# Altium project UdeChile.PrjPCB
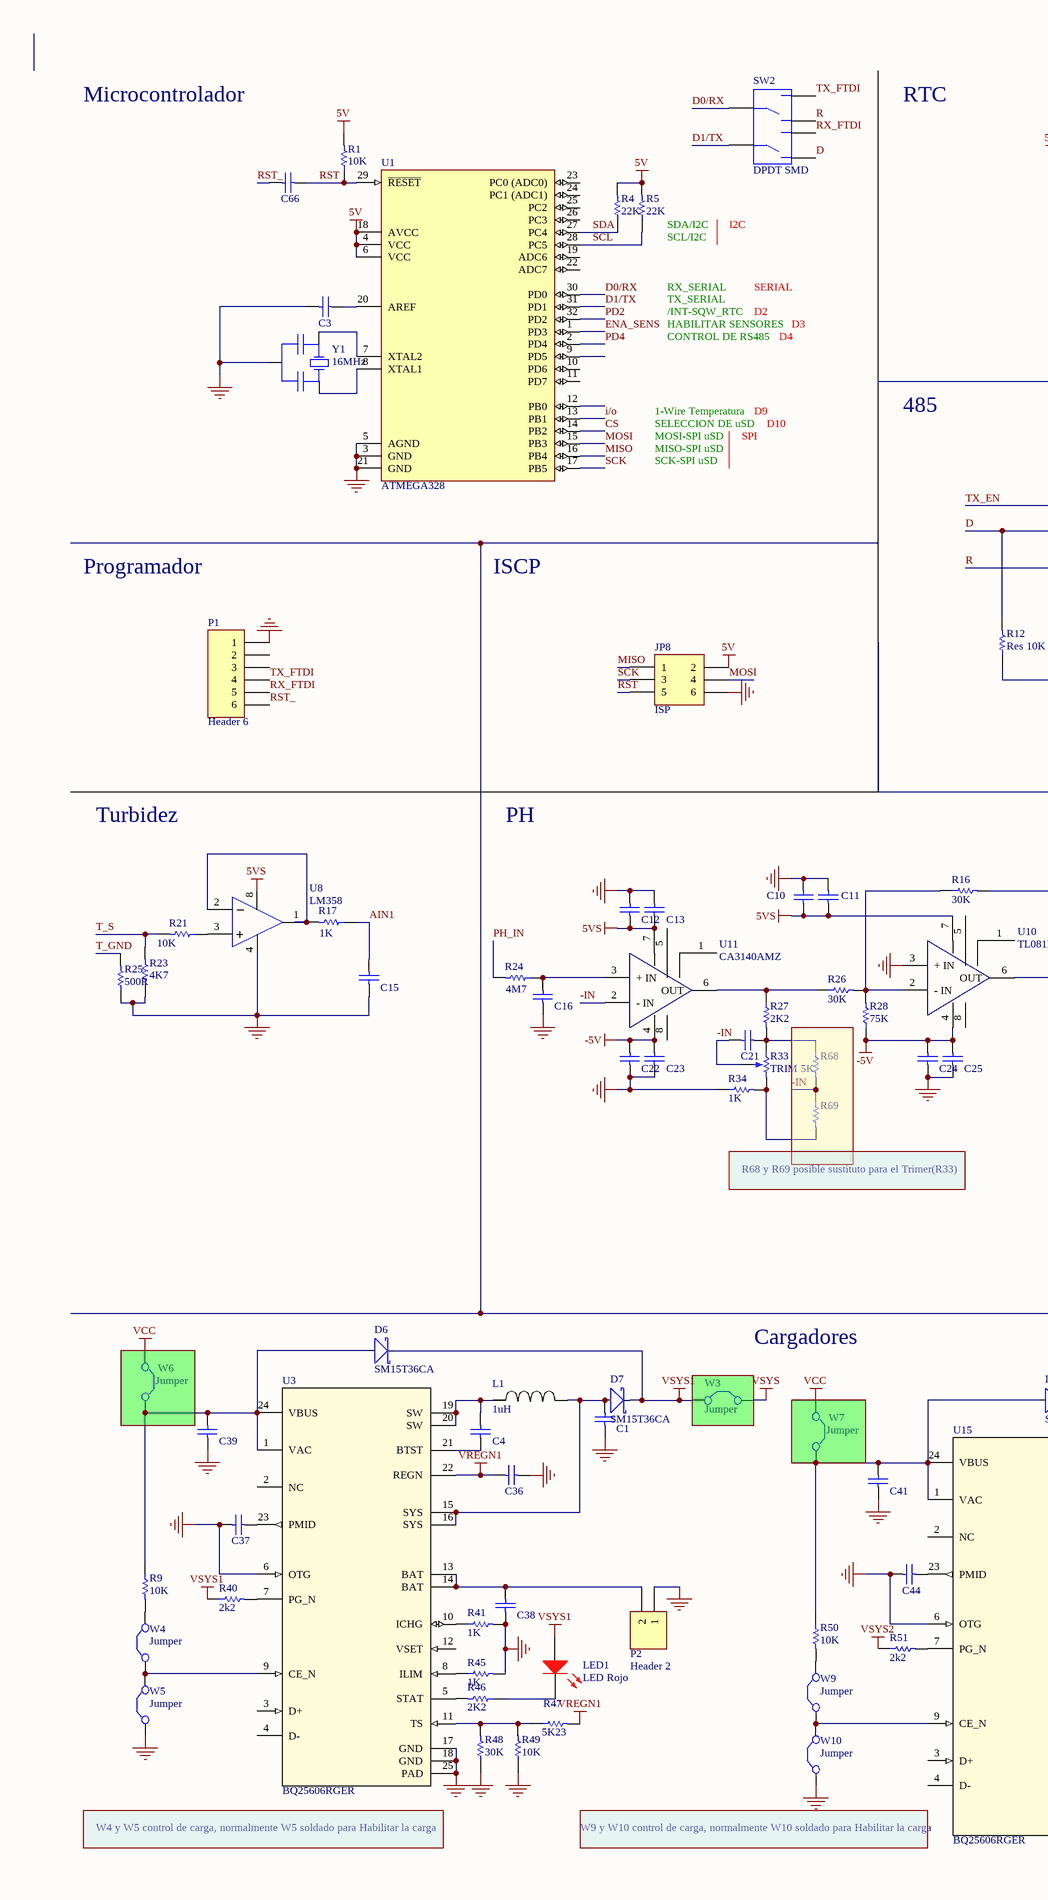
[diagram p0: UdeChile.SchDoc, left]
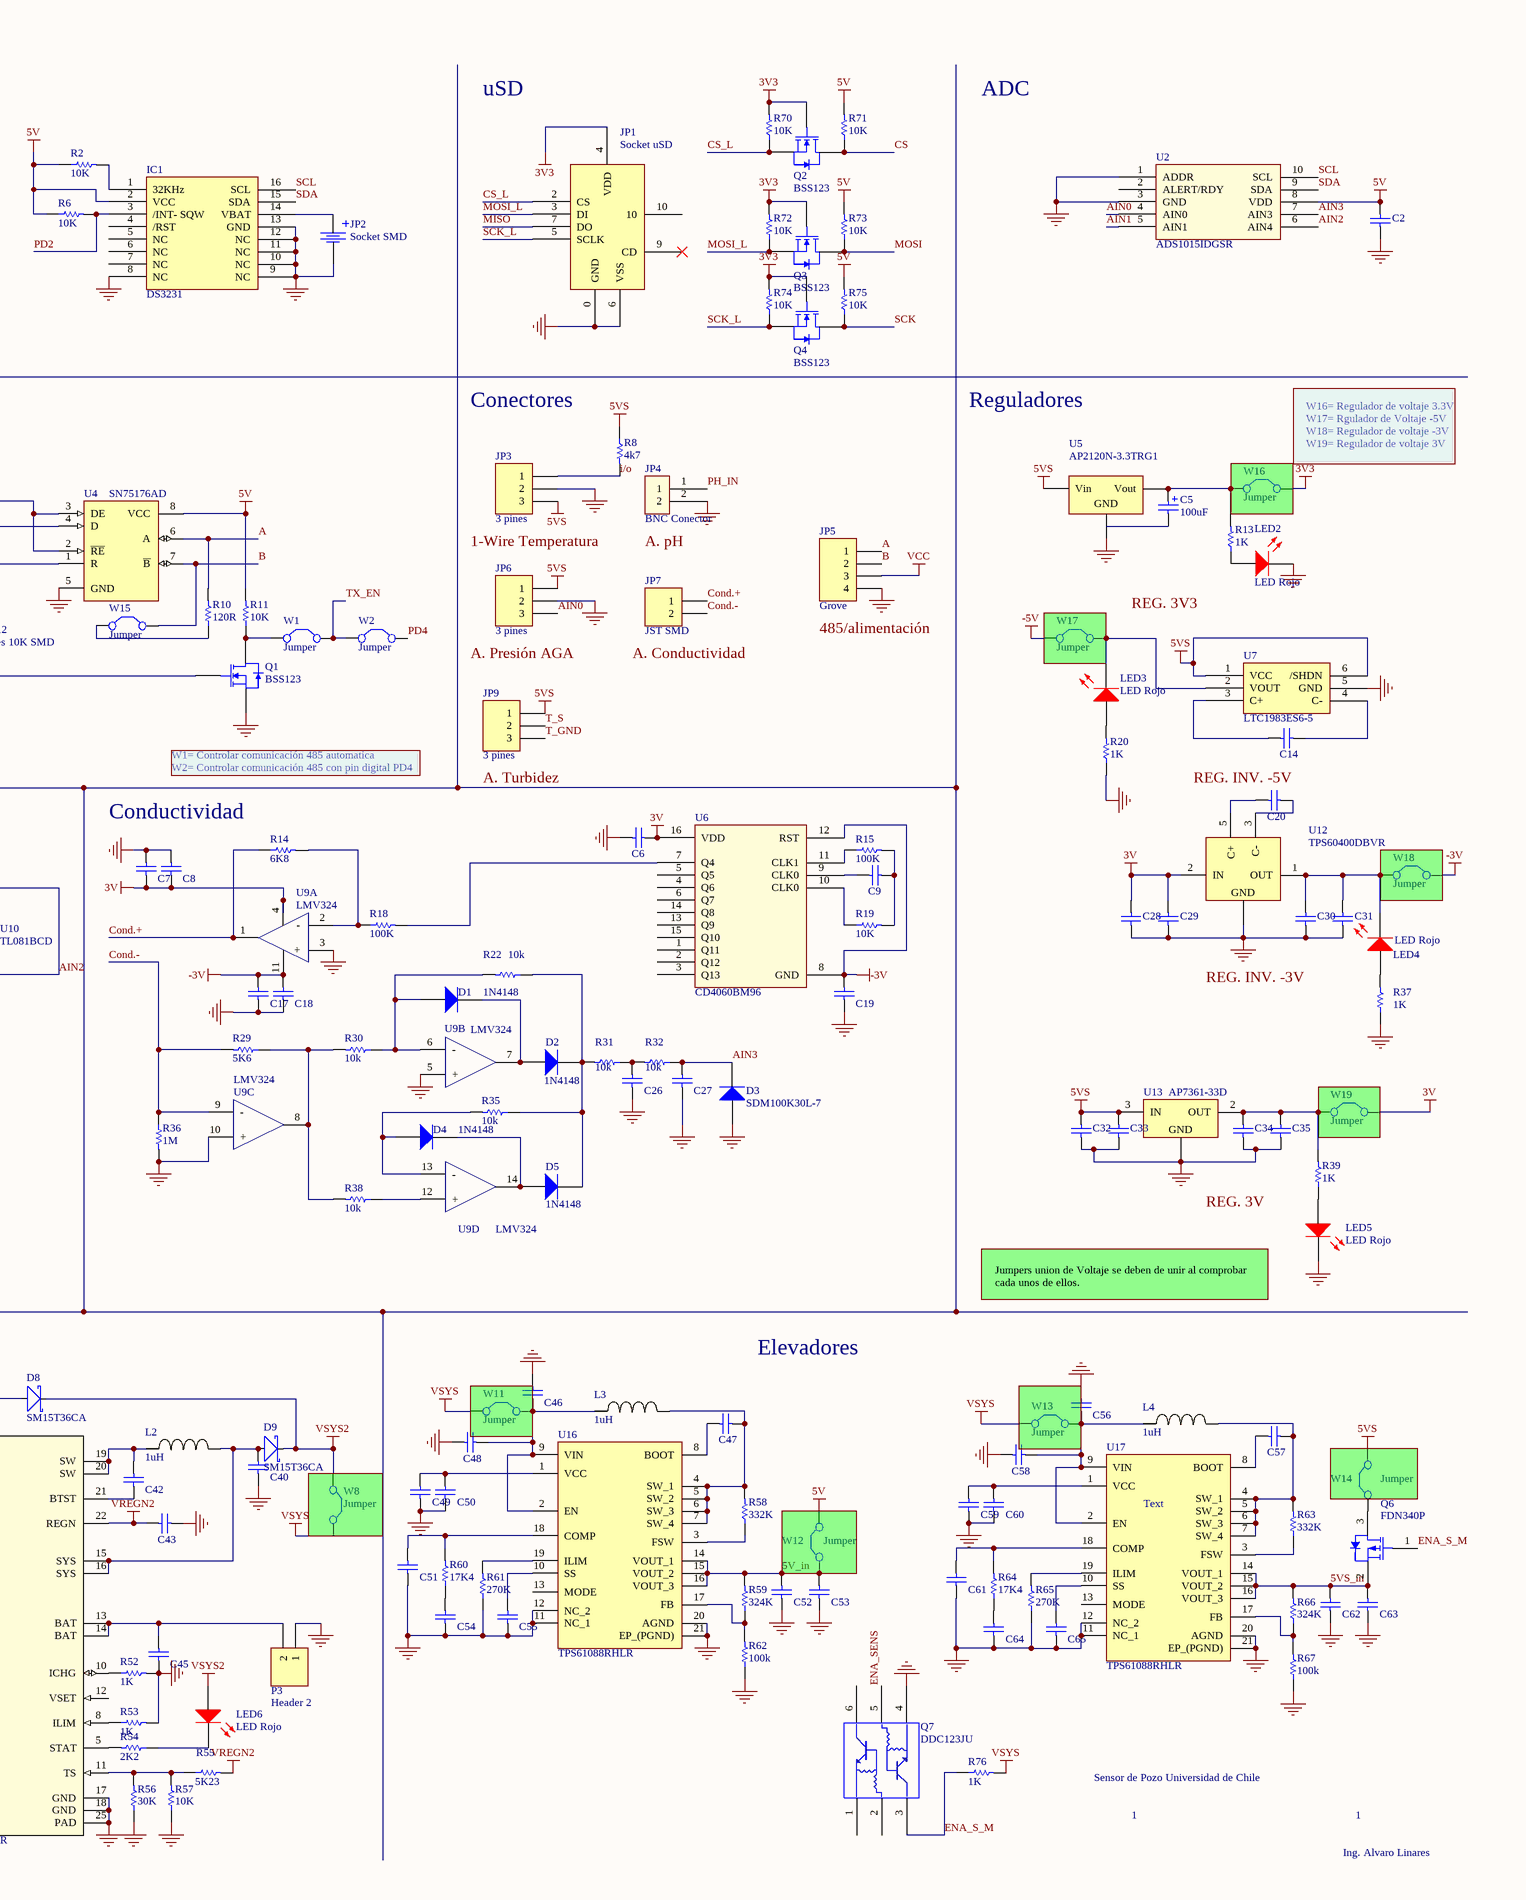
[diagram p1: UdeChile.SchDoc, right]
1 sheet, 212 parts. Net scope: global (net labels, ports and power ports of the same name join across sheets).
Board file: UdeChile.PcbDoc

## Sheet UdeChile.SchDoc
size C

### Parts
C1  0.1uF  [Cap 0.1uF 0603 SMD]  (value not drawn)
C2  0.1uF  [Cap 0.1uF 0603 SMD]  (value not drawn)
C3  0.1uF  [Cap 0.1uF 0603 SMD]  (value not drawn)
C4  47nF  [Cap 0.1uF 0603 SMD]  (value not drawn)
C5  100uF  [Cap tant 10uF 1206 SMD]
C6  0.1uF  [Cap 0.1uF 0603 SMD]  (value not drawn)
C7  4.7uF  [Cap 0.1uF 0603 SMD]  (value not drawn)
C8  0.1uF  [Cap 0.1uF 0603 SMD]  (value not drawn)
C9  1nF  [Cap 0.1uF 0603 SMD]  (value not drawn)
C10  0.1uF  [Cap 0.1uF 0603 SMD]  (value not drawn)
C11  10uF  [Cap 0.1uF 0603 SMD]  (value not drawn)
C12  0.1uF  [Cap 0.1uF 0603 SMD]  (value not drawn)
C13  10uF  [Cap 0.1uF 0603 SMD]  (value not drawn)
C14  0.1uF  [Cap 0.1uF 0603 SMD]  (value not drawn)
C15  0.1uF  [Cap 0.1uF 0603 SMD]  (value not drawn)
C16  2.2nF  [Cap 0.1uF 0603 SMD]  (value not drawn)
C17  4.7uF  [Cap 0.1uF 0603 SMD]  (value not drawn)
C18  0.1uF  [Cap 0.1uF 0603 SMD]  (value not drawn)
C19  0.1uF  [Cap 0.1uF 0603 SMD]  (value not drawn)
C20  0.1uF  [Cap 0.1uF 0603 SMD]  (value not drawn)
C21  1uF  [Cap 0.1uF 0603 SMD]  (value not drawn)
C22  0.1uF  [Cap 0.1uF 0603 SMD]  (value not drawn)
C23  10uF  [Cap 0.1uF 0603 SMD]  (value not drawn)
C24  0.1uF  [Cap 0.1uF 0603 SMD]  (value not drawn)
C25  10uF  [Cap 0.1uF 0603 SMD]  (value not drawn)
C26  1uF  [Cap 0.1uF 0603 SMD]  (value not drawn)
C27  1uF  [Cap 0.1uF 0603 SMD]  (value not drawn)
C28  0.1uF  [Cap 0.1uF 0603 SMD]  (value not drawn)
C29  0.1uF  [Cap 0.1uF 0603 SMD]  (value not drawn)
C30  0.1uF  [Cap 0.1uF 0603 SMD]  (value not drawn)
C31  0.1uF  [Cap 0.1uF 0603 SMD]  (value not drawn)
C32  0.1uF  [Cap 0.1uF 0603 SMD]  (value not drawn)
C33  0.1uF  [Cap 0.1uF 0603 SMD]  (value not drawn)
C34  0.1uF  [Cap 0.1uF 0603 SMD]  (value not drawn)
C35  0.1uF  [Cap 0.1uF 0603 SMD]  (value not drawn)
C36  4.7uF  [Cap 0.1uF 0603 SMD]  (value not drawn)
C37  10uF  [Cap 0.1uF 0603 SMD]  (value not drawn)
C38  10uF  [Cap 0.1uF 0603 SMD]  (value not drawn)
C39  10uF  [Cap 0.1uF 0603 SMD]  (value not drawn)
C40  0.1uF  [Cap 0.1uF 0603 SMD]  (value not drawn)
C41  10uF  [Cap 0.1uF 0603 SMD]  (value not drawn)
C42  47nF  [Cap 0.1uF 0603 SMD]  (value not drawn)
C43  4.7uF  [Cap 0.1uF 0603 SMD]  (value not drawn)
C44  10uF  [Cap 0.1uF 0603 SMD]  (value not drawn)
C45  10uF  [Cap 0.1uF 0603 SMD]  (value not drawn)
C46  0.1uF  [Cap 0.1uF 0603 SMD]  (value not drawn)
C47  0.1uF  [Cap 0.1uF 0603 SMD]  (value not drawn)
C48  47uF  [Cap 0.1uF 0603 SMD]  (value not drawn)
C49  1uF  [Cap 0.1uF 0603 SMD]  (value not drawn)
C50  1uF  [Cap 0.1uF 0603 SMD]  (value not drawn)
C51  51pF  [Cap 0.1uF 0603 SMD]  (value not drawn)
C52  47uF  [Cap 0.1uF 0603 SMD]  (value not drawn)
C53  47uF  [Cap 0.1uF 0603 SMD]  (value not drawn)
C54  1nF  [Cap 0.1uF 0603 SMD]  (value not drawn)
C55  82nF  [Cap 0.1uF 0603 SMD]  (value not drawn)
C56  0.1uF  [Cap 0.1uF 0603 SMD]  (value not drawn)
C57  0.1uF  [Cap 0.1uF 0603 SMD]  (value not drawn)
C58  47uF  [Cap 0.1uF 0603 SMD]  (value not drawn)
C59  1uF  [Cap 0.1uF 0603 SMD]  (value not drawn)
C60  1uF  [Cap 0.1uF 0603 SMD]  (value not drawn)
C61  51pF  [Cap 0.1uF 0603 SMD]  (value not drawn)
C62  47uF  [Cap 0.1uF 0603 SMD]  (value not drawn)
C63  47uF  [Cap 0.1uF 0603 SMD]  (value not drawn)
C64  1nF  [Cap 0.1uF 0603 SMD]  (value not drawn)
C65  82nF  [Cap 0.1uF 0603 SMD]  (value not drawn)
C66  0.1uF  [Cap 0.1uF 0603 SMD]  (value not drawn)
D1  1N4148  [Diodo 1N4148 SMD]
D2  1N4148  [Diodo 1N4148 SMD]
D3  SDM100K30L-7  [Diodo SDM100K30L-7 SMD]
D4  1N4148  [Diodo 1N4148 SMD]
D5  1N4148  [Diodo 1N4148 SMD]
D6  SM15T36CA  [SM15T36CA]
D7  SM15T36CA  [SM15T36CA]
D8  SM15T36CA  [SM15T36CA]
D9  SM15T36CA  [SM15T36CA]
IC1  DS3231  [RTC DS323116-SOIC]
JP1  Socket uSD  [uSD Socket]
JP2  Socket SMD  [Socket Pila 12mm SMD]
JP3  3 pines  [JST SMD 3 PINES]
JP4  BNC Conector  [BNC Conector]
JP5  Grove  [JST TH 4 Pines - Horizontal]
JP6  3 pines  [JST SMD 3 PINES]
JP7  JST SMD  [JST SMD 2 pines - 2.54mm]
JP8  ISP  [HDR2X3]
JP9  3 pines  [JST SMD 3 PINES - 2.54mm]
L1  1uH  [74438336010]
L2  1uH  [74438336010]
L3  1uH  [SRN8040-1R0Y]
L4  1uH  [SRN8040-1R0Y]
LED1  LED Rojo  [LED Rojo 0603]
LED2  LED Rojo  [LED Rojo 0603]
LED3  LED Rojo  [LED Rojo 0603]
LED4  LED Rojo  [LED Rojo 0603]
LED5  LED Rojo  [LED Rojo 0603]
LED6  LED Rojo  [LED Rojo 0603]
P1  Header 6  [HDR1X6]
P2  Header 2  [HDR1X2]
P3  Header 2  [HDR1X2]
Q1  BSS123  [MOSFET BSS123  SMD SOT-23]
Q2  BSS123  [MOSFET BSS123  SMD SOT-23]
Q3  BSS123  [MOSFET BSS123  SMD SOT-23]
Q4  BSS123  [MOSFET BSS123  SMD SOT-23]
Q6  FDN340P  [MOSFET FDN340P SSOT3]
Q7  DDC123JU  [Transistor array DDC123JU-FDICT SMD]
R1  10K  [Res 1K 0603 1/8W]
R2  10K  [Res 10K 0603 1/10W]
R4  22K  [Res 1K 0603 1/8W]
R5  22K  [Res 1K 0603 1/8W]
R6  10K  [Res 10K 0603 1/10W]
R8  4k7  [Res 10K 0603 1/10W]
R9  10K  [Res 1K 0603 1/8W]
R10  120R  [Res 1K 0603 1/8W]
R11  10K  [Res 10K 0603 1/10W]
R12  Res 10K SMD  [Res 10K 0603 1/10W]
R13  1K  [Res 1K 0603 1/8W]
R14  6K8  [Res 1K 0603 1/8W]
R15  100K  [Res 1K 0603 1/8W]
R16  30K  [Res 1K 0603 1/8W]
R17  1K  [Res 1K 0603 1/8W]
R18  100K  [Res 1K 0603 1/8W]
R19  10K  [Res 1K 0603 1/8W]
R20  1K  [Res 1K 0603 1/8W]
R21  10K  [Res 1K 0603 1/8W]
R22  10k  [Res 1K 0603 1/8W]
R23  4K7  [Res 1K 0603 1/8W]
R24  4M7  [Res 1K 0603 1/8W]
R25  500R  [Res 1K 0603 1/8W]
R26  30K  [Res 1K 0603 1/8W]
R27  2K2  [Res 1K 0603 1/8W]
R28  75K  [Res 1K 0603 1/8W]
R29  5K6  [Res 1K 0603 1/8W]
R30  10k  [Res 1K 0603 1/8W]
R31  10k  [Res 1K 0603 1/8W]
R32  10k  [Res 1K 0603 1/8W]
R33  TRIM 5K  [TRIMPOT TH]
R34  1K  [Res 1K 0603 1/8W]
R35  10k  [Res 1K 0603 1/8W]
R36  1M  [Res 1K 0603 1/8W]
R37  1K  [Res 1K 0603 1/8W]
R38  10k  [Res 1K 0603 1/8W]
R39  1K  [Res 1K 0603 1/8W]
R40  2k2  [Res 1K 0603 1/8W]
R41  1K  [Res 1K 0603 1/8W]
R45  1K  [Res 1K 0603 1/8W]
R46  2K2  [Res 1K 0603 1/8W]
R47  5K23  [Res 1K 0603 1/8W]
R48  30K  [Res 1K 0603 1/8W]
R49  10K  [Res 1K 0603 1/8W]
R50  10K  [Res 1K 0603 1/8W]
R51  2k2  [Res 1K 0603 1/8W]
R52  1K  [Res 1K 0603 1/8W]
R53  1K  [Res 1K 0603 1/8W]
R54  2K2  [Res 1K 0603 1/8W]
R55  5K23  [Res 1K 0603 1/8W]
R56  30K  [Res 1K 0603 1/8W]
R57  10K  [Res 1K 0603 1/8W]
R58  332K  [Res 1K 0603 1/8W]
R59  324K  [Res 1K 0603 1/8W]
R60  17K4  [Res 1K 0603 1/8W]
R61  270K  [Res 1K 0603 1/8W]
R62  100k  [Res 1K 0603 1/8W]
R63  332K  [Res 1K 0603 1/8W]
R64  17K4  [Res 1K 0603 1/8W]
R65  270K  [Res 1K 0603 1/8W]
R66  324K  [Res 1K 0603 1/8W]
R67  100k  [Res 1K 0603 1/8W]
R68  0  [Res 1K 0603 1/8W]  (value not drawn)
R69  0  [Res 1K 0603 1/8W]  (value not drawn)
R70  10K  [Res 10K 0603 1/10W]
R71  10K  [Res 10K 0603 1/10W]
R72  10K  [Res 10K 0603 1/10W]
R73  10K  [Res 10K 0603 1/10W]
R74  10K  [Res 10K 0603 1/10W]
R75  10K  [Res 10K 0603 1/10W]
R76  1K  [Res 1K 0603 1/8W]
SW2  DPDT SMD  [SW INTERR SMD]
U1  ATMEGA328  [ATMega328 32-TQFP SMD]
U2  ADS1015IDGSR  [ADS1015IDGSR]
U3  BQ25606RGER  [BQ25606RGER]
U4  SN75176AD  [Transceiver SN75176AD SOCI8]
U5  AP2120N-3.3TRG1  [Reg 3.3V 150mA SOT-23]
U6  CD4060BM96  [C BINARY COUNTER/DIV/OSC CD4060BM 16SOIC]
U7  LTC1983ES6-5  [Reg CHARGE PUMP -5V SOT-23-6]
U8  LM358  [Op Amp LM358 8-SOIC SMD]
U9  LMV324  [Op. Amp LM324 SO-14]  (parts A,B,C,D of 4)
U10  TL081BCD  [Amp. Op. CA3140AMZ SOIC8]
U11  CA3140AMZ  [Amp. Op. CA3140AMZ SOIC8]
U12  TPS60400DBVR  [Charge Pump Switching Regulator - TPS60400DBVR]
U13  AP7361-33D  [Reg 3V 300mA SOT23-3]
U15  BQ25606RGER  [BQ25606RGER]
U16  TPS61088RHLR  [TPS61088RHLR]
U17  TPS61088RHLR  [TPS61088RHLR]
W1  Jumper  [Jumper]
W2  Jumper  [Jumper]
W3  Jumper  [Jumper]
W4  Jumper  [Jumper]
W5  Jumper  [Jumper]
W6  Jumper  [Jumper]
W7  Jumper  [Jumper]
W8  Jumper  [Jumper]
W9  Jumper  [Jumper]
W10  Jumper  [Jumper]
W11  Jumper  [Jumper]
W12  Jumper  [Jumper]
W13  Jumper  [Jumper]
W14  Jumper  [Jumper]
W15  Jumper  [Jumper]
W16  Jumper  [Jumper]
W17  Jumper  [Jumper]
W18  Jumper  [Jumper]
W19  Jumper  [Jumper]
Y1  16MHz  [Xtal 16MHz SMD]

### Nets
3V: C6.1 C7.2 C8.2 C28.2 C29.2 U6.16(VDD) U9.4(V+) U12.2(IN) W19.2
3V3: JP1.4(VDD) Q2.1(G) Q3.1(G) Q4.1(G) R70.2 R72.2 R74.2 W16.2
5V: C2.2 IC1.2(VCC) JP8.2 R1.2 R2.1 R4.2 R5.2 R6.1 R11.2 R71.2 R73.2 R75.2 U1.4(VCC) U1.6(VCC) U1.18(AVCC) U2.8(VDD) U4.8(VCC) W12.2
5VS: C10.2 C11.2 C12.2 C13.2 C32.2 C33.2 JP3.3 JP6.1 JP9.1 R8.1 U5.3(Vin) U7.1(VCC) U7.6(/SHDN) U8.8(VCC) U10.7 U11.7 U13.3(IN) W14.2
-3V: C17.1 C18.1 C19.1 U6.8(GND) U6.12(RST) U9.11(V-) W18.2
-5V: C22.1 C23.1 C24.1 C25.1 R28.1 U10.4 U11.4 W17.1
GND: C1.1 C2.1 C3.1 C6.2 C7.1 C8.1 C10.1 C11.1 C12.1 C13.1 C15.2 C16.2 C17.2 C18.2 C19.2 C22.2 C23.2 C24.2 C25.2 C26.2 C27.2 C28.1 C29.1 C30.1 C31.1 C32.1 C33.1 C34.1 C35.1 C36.2 C37.1 C38.1 C39.1 C40.1 C41.1 C43.2 C44.1 C45.1 C46.2 C48.1 C49.2 C50.2 C51.2 C52.2 C53.2 C54.2 C55.2 C56.2 C58.1 C59.2 C60.2 C61.2 C62.2 C63.2 C64.2 C65.2 D3.1(A) IC1.8(NC) IC1.9(NC) IC1.10(NC) IC1.11(NC) IC1.12(NC) IC1.13(GND) JP1.0(GND) JP1.6(VSS) JP2.2(-) JP3.2 JP4.2 JP5.4 JP6.2 JP8.6 LED2.2(K) LED5.2(K) P1.1 P2.1 P3.1 Q1.2(S) Q7.4 R20.1 R23.1 R25.1 R34.1 R36.2 R37.1 R41.2 R45.2 R48.1 R49.1 R52.2 R53.2 R56.1 R57.1 R61.1 R62.1 R65.1 R67.1 U1.3(GND) U1.5(AGND) U1.21(GND) U2.1(ADDR) U2.3(GND) U3.6(OTG) U3.17(GND) U3.18(GND) U3.25(PAD) U4.5(GND) U5.1(GND) U7.5(GND) U8.4(GND) U9.3(+) U9.5(+) U9.10(+) U10.3(+_IN) U12.4(GND) U13.1(GND) U15.6(OTG) U15.17(GND) U15.18(GND) U15.25(PAD) U16.11(NC_1) U16.12(NC_2) U16.20(AGND) U16.21(EP_(PGND)) U17.11(NC_1) U17.12(NC_2) U17.20(AGND) U17.21(EP_(PGND)) W5.1 W10.1 Y1.2(GND)
VCC: JP5.3 W6.1 W7.1
VREGN1: C36.1 R47.2 U3.22(REGN)
VREGN2: C43.1 R55.2 U15.22(REGN)
VSYS: R76.2 W3.2 W8.2 W11.1 W13.1
VSYS1: D6.1(K) D7.1(K) LED1.1(A) R40.1 W3.1
VSYS2: D8.1(K) D9.1(K) LED6.1(A) R51.1 W8.1
5V_in: C52.1 C53.1 R59.2 U16.14(VOUT_1) U16.15(VOUT_2) U16.16(VOUT_3) W12.1
5VS_in: C62.1 C63.1 Q6.2(S) R66.2 U17.14(VOUT_1) U17.15(VOUT_2) U17.16(VOUT_3)
-IN: C21.2 R33.2(TAP) R68.2 R69.1 U11.2(-_IN)
A: JP5.1 R10.2 U4.6(A)
AIN0: JP6.3 U2.4(AIN0)
AIN1: C15.1 R17.1 U2.5(AIN1)
AIN2: R16.2 U2.6(AIN4) U10.6(OUT)
AIN3: C27.1 D3.2(K) R32.1 U2.7(AIN3)
B: JP5.2 U4.7(~{B}) W15.2
Cond.+: JP7.1 R14.1 U9.1(out)
Cond.-: JP7.2 R29.2 R36.1 U9.9(-)
CS: Q2.3(D) R71.1 U1.14(PB2)
CS_L: JP1.2(CS) Q2.2(S) R70.1
D: R12.2 SW2.4 U4.4(D)
D0/RX: SW2.2 U1.30(PD0)
D1/TX: SW2.5 U1.31(PD1)
ENA_S_M: Q6.1(G) Q7.3 R76.1
ENA_SENS: Q7.5 U1.1(PD3)
i/o: JP3.1 R8.2 U1.13(PB1)
MISO: JP1.7(DO) JP8.1 U1.16(PB4)
MOSI: JP8.4 Q3.3(D) R73.1 U1.15(PB3)
MOSI_L: JP1.3(DI) Q3.2(S) R72.1
PD2: IC1.3(/INT-_SQW) R6.2 U1.32(PD2)
PD4: U1.2(PD4) W2.2
PH_IN: JP4.1 R24.2
R: SW2.3 U4.1(R)
RST: C66.1 JP8.5 R1.1 U1.29(~{RESET})
RST_: C66.2 P1.6
RX_FTDI: P1.5 SW2.6
SCK: JP8.3 Q4.3(D) R75.1 U1.17(PB5)
SCK_L: JP1.5(SCLK) Q4.2(S) R74.1
SCL: IC1.16(SCL) R5.1 U1.28(PC5) U2.10(SCL)
SDA: IC1.15(SDA) R4.1 U1.27(PC4) U2.9(SDA)
T_GND: JP9.3 R25.2
T_S: JP9.2 R21.2 R23.2
TX_EN: U4.2(~{RE}) U4.3(DE) W1.2 W2.1
TX_FTDI: P1.4 SW2.1
NetC1_2: C1.2 D7.2(A) L1.2 U3.15(SYS) U3.16(SYS)
NetC3_2: C3.2 U1.20(AREF)
NetC4_1: C4.1 U3.21(BTST)
NetC4_2: C4.2 L1.1 U3.19(SW) U3.20(SW)
NetC5_1: C5.1 R13.2 U5.2(Vout) W16.1
NetC9_1: C9.1 U6.9(CLK0)
NetC9_2: C9.2 R15.2 R19.2
NetC14_1: C14.1 U7.4(C-)
NetC14_2: C14.2 U7.3(C+)
NetC16_1: C16.1 R24.1 U11.3(+_IN)
NetC20_1: C20.1 U12.3(C-)
NetC20_2: C20.2 U12.5(C+)
NetC21_1: C21.1 R27.2 R33.1(TOP) R68.1
NetC26_1: C26.1 R31.1 R32.2
NetC30_2: C30.2 C31.2 LED4.2(K) U12.1(OUT) W18.1
NetC34_2: C34.2 C35.2 R39.2 U13.2(OUT) W19.1
NetC37_2: C37.2 U3.23(PMID)
NetC38_2: C38.2 P2.2 U3.13(BAT) U3.14(BAT)
NetC39_2: C39.2 D6.2(A) R9.1 U3.1(VAC) U3.24(VBUS) W6.2
NetC40_2: C40.2 D9.2(A) L2.2 U15.15(SYS) U15.16(SYS)
NetC41_2: C41.2 D8.2(A) R50.1 U15.1(VAC) U15.24(VBUS) W7.2
NetC42_1: C42.1 U15.21(BTST)
NetC42_2: C42.2 L2.1 U15.19(SW) U15.20(SW)
NetC44_2: C44.2 U15.23(PMID)
NetC45_2: C45.2 P3.2 U15.13(BAT) U15.14(BAT)
NetC46_1: C46.1 C48.2 L3.1 U16.2(EN) U16.9(VIN) W11.2
NetC47_1: C47.1 L3.2 R58.2 U16.4(SW_1) U16.5(SW_2) U16.6(SW_3) U16.7(SW_4)
NetC47_2: C47.2 U16.8(BOOT)
NetC49_1: C49.1 C50.1 U16.1(VCC)
NetC51_1: C51.1 R60.2 U16.18(COMP)
NetC54_1: C54.1 R60.1
NetC55_1: C55.1 U16.10(SS)
NetC56_1: C56.1 C58.2 L4.1 U17.2(EN) U17.9(VIN) W13.2
NetC57_1: C57.1 L4.2 R63.2 U17.4(SW_1) U17.5(SW_2) U17.6(SW_3) U17.7(SW_4)
NetC57_2: C57.2 U17.8(BOOT)
NetC59_1: C59.1 C60.1 U17.1(VCC)
NetC61_1: C61.1 R64.2 U17.18(COMP)
NetC64_1: C64.1 R64.1
NetC65_1: C65.1 U17.10(SS)
NetD1_1: D1.1(A) R22.2 R30.1 U9.6(-)
NetD1_2: D1.2(K) D2.1(A) U9.7(out2)
NetD2_2: D2.2(K) D5.2(K) R22.1 R31.2 R35.1
NetD4_1: D4.1(A) R35.2 U9.13(-)
NetD4_2: D4.2(K) D5.1(A) U9.14(out4)
NetIC1_1: IC1.1(32KHz) R2.2
NetIC1_14: IC1.14(VBAT) JP2.1(+)
NetLED1_2: LED1.2(K) R46.1
NetLED2_1: LED2.1(A) R13.1
NetLED3_1: LED3.1(A) R20.2
NetLED3_2: LED3.2(K) U7.2(VOUT) W17.2
NetLED4_1: LED4.1(A) R37.2
NetLED5_1: LED5.1(A) R39.1
NetLED6_2: LED6.2(K) R54.1
NetQ1_1: Q1.1(G) R12.1
NetQ1_3: Q1.3(D) R11.1 W1.1
NetQ6_3: Q6.3(D) W14.1
NetR9_2: R9.2 W4.2
NetR10_1: R10.1 W15.1
NetR14_2: R14.2 R18.1 U9.2(-)
NetR15_1: R15.1 U6.11(CLK1)
NetR16_1: R16.1 R26.2 R28.2 U10.2(-_IN)
NetR17_2: R17.2 U8.1(OUT1) U8.2(IN1_-)
NetR18_2: R18.2 U6.7(Q4)
NetR19_1: R19.1 U6.10(CLK0)
NetR21_1: R21.1 U8.3(IN1_+)
NetR26_1: R26.1 R27.1 U11.6(OUT)
NetR29_1: R29.1 R30.2 R38.2 U9.8(out3)
NetR33_3: R33.3(BOT) R34.2 R69.2
NetR38_1: R38.1 U9.12(+)
NetR40_2: R40.2 U3.7(PG_N)
NetR41_1: R41.1 U3.10(ICHG)
NetR45_1: R45.1 U3.8(ILIM)
NetR46_2: R46.2 U3.5(STAT)
NetR47_1: R47.1 R48.2 R49.2 U3.11(TS)
NetR50_2: R50.2 W9.2
NetR51_2: R51.2 U15.7(PG_N)
NetR52_1: R52.1 U15.10(ICHG)
NetR53_1: R53.1 U15.8(ILIM)
NetR54_2: R54.2 U15.5(STAT)
NetR55_1: R55.1 R56.2 R57.2 U15.11(TS)
NetR58_1: R58.1 U16.3(FSW)
NetR59_1: R59.1 R62.2 U16.17(FB)
NetR61_2: R61.2 U16.19(ILIM)
NetR63_1: R63.1 U17.3(FSW)
NetR65_2: R65.2 U17.19(ILIM)
NetR66_1: R66.1 R67.2 U17.17(FB)
NetU1_7: U1.7(XTAL2) Y1.3(OSC2)
NetU1_8: U1.8(XTAL1) Y1.1(OSC1)
NetU3_9: U3.9(CE_N) W4.1 W5.2
NetU15_9: U15.9(CE_N) W9.1 W10.2

Not connected (* = marked no-connect by the designer): C5 2; IC1 4(/RST) 5(NC) 6(NC) 7(NC); JP1 9(CD)* 10; JP3 4 5; JP6 4 5; JP7 3 4; JP9 4 5; P1 2 3; Q7 1 2 6; SW2 7 8; U1 9(PD5) 10(PD6) 11(PD7) 12(PB0) 19(ADC6) 22(ADC7) 23(PC0_(ADC0)) 24(PC1_(ADC1)) 25(PC2) 26(PC3); U2 2(ALERT/RDY); U3 2(NC) 3(D+) 4(D-) 12(VSET); U6 1(Q11) 2(Q12) 3(Q13) 4(Q6) 5(Q5) 6(Q7) 13(Q9) 14(Q8) 15(Q10); U10 1 5 8; U11 1 5 8; U15 2(NC) 3(D+) 4(D-) 12(VSET); U16 13(MODE); U17 13(MODE)

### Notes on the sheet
- Microcontrolador
- RTC
- uSD
- ADC
- (near R5) SDA/I2C
- (near R5) SCL/I2C
- I2C
- RX_SERIAL
- TX_SERIAL
- SERIAL
- /INT-SQW_RTC
- HABILITAR SENSORES
- CONTROL DE RS485
- D2
- D4
- D3
- 1-Wire Temperatura
- SELECCION DE uSD
- D9
- D10
- 485
- Conectores
- Reguladores
- W16= Regulador de voltaje 3.3V
- W17= Rgulador de Voltaje -5V
- MOSI-SPI uSD
- MISO-SPI uSD
- SCK-SPI uSD
- SPI
- W18= Regulador de voltaje -3V
- (near W16) W19= Regulador de voltaje 3V
- A. pH
- Programador
- ISCP
- REG. 3V3
- A. Presión AGA
- (near JP7) A. Conductividad
- (near JP5) 485/alimentación
- W1= Controlar comunicación 485 automatica
- W2= Controlar comunicación 485 con pin digital PD4
- (near JP9) A. Turbidez
- (near C20) REG. INV. -5V
- Turbidez
- PH
- Conductividad
- REG. INV. -3V
- (near R69) R68 y R69 posible sustituto para el Trimer(R33)
- REG. 3V
- Jumpers union de Voltaje se deben de unir al comprobar cada unos de ellos.
- Cargadores
- Elevadores
- (near U17) Text
- Sensor de Pozo Universidad de Chile
- W4 y W5 control de carga, normalmente W5 soldado para Habilitar la carga
- (near U15) W9 y W10 control de carga, normalmente W10 soldado para Habilitar la carga
- 1
- Ing. Alvaro Linares

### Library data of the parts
C1-C4 C6 C8-C13 C15 C17 C19 C21-C25 C28 C30 C32 C34 C36-C66 = Capacitor 0.1uF SMD: 0.1uF 16V
C5 = Cap TANT 100uF: CAP TANT 100UF 6.3V 20% 1206
C7 C18 C26 C27 = Capacitor 0.1uF SMD
C14 C20 = Capacitor 0.1uF SMD: 1uF 16V
C16 = Capacitor 0.1uF SMD: 2.2nF 16V
C29 C31 C33 C35 = Capacitor 0.1uF SMD: 10uF 16V
D1 D2 D4 D5 = Diodo 4148: Diodo 4148 SMD
D3 = Diodo SDM100K30L-7: Diodo SDM100K30L-7 SMD
D6-D9 = SM15T36CA: TVS DIODE 30.8V 64.3V SMC
IC1 = DS3231: IC RTC CLK/CALENDAR I2C 16-SOIC
JP2 = Socket Pila 12mm SMD
JP3 JP6 = JST 3 pines: 485-4391
JP5 = JST 4 pines_Horizontal: 713-110990037
JP7 = JST 2 pines_2.54mm: 2 pines
JP8 = Header 3X2: Header, 3-Pin, Dual row
JP9 = JST 3 pines 2.54mm
L1 L2 = 74438336010: FIXED IND 1UH 4A 32 MOHM SMD
L3 L4 = SRN8040-1R0Y: FIXED IND 1UH 7.8A 10 MOHM SMD
LED1-LED6 = LED Rojo: LED Rojo 0603
P1 = Header 6: Header, 6-Pin
P2 P3 = Header 2: Header, 2-Pin
Q1-Q4 = MOSFET N-Channel_2: MOSFET N-CH 100V 170MA
Q6 = MOSFET P-Channel_3: MOSFET P-CH 20V 2A SSOT3
Q7 = Trans Array Dual NPN: Transistor Array 100mA
R1 R4 R5 R9 R10 R13-R32 R34-R41 R45-R69 R76 = Res 1K SMD: 1K SMD
R2 R6 R11 R70-R75 = Res 10K SMD
R8 R12 = Res 10K SMD: 10K
R33 = TRIMMER 10K OHM: TRIMMER 10K OHM 0.5W PC PIN
SW2 = SW interruptor
U1 = ATMEGA328: IC ATMega328; MCI: MCI-GEN-
U3 U15 = BQ25606RGER: IC BATT CHG LI-ION 1 CELL 24VQFN
U4 = SN75176AD: Transceiver Differential Bus 5V; Package Information: Latest Revision: Jan-1998; Note: Receiver Hysteresis of 50mV Typical
U5 = Reg 3.3V 150mA AP2120N: IC REG LINEAR 3.3V 150MA SOT23
U6 = IC Binary Counter Element Bit Negative
U7 = LTC1983ES6-5: REG CHARGE PUMP -5V TSOT23-6
U8 = Op Amp 358: Op Amp LM358
U9 = LMV324: Op. Amp. GP 4 CIRCUIT 14SO
U10 = TL081BCD: Operational Amplifier
U11 = CA3140AMZ: Operational Amplifier with MOSFET
U12 = TPS60400 60MA CHARGE PUMP VOLTAG: Reg. inv. -3v
U13 = REG LINEAR 3V 300MA SOT23-3: Regulador 3 0.3mA AP2125N-3.0TRG1
U16 U17 = TPS61088RHLR: IC REG BOOST ADJ 10A 20VQFN
W1-W19 = Jumper: Jumper Wire
Y1 = XTAL 16MHz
